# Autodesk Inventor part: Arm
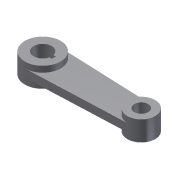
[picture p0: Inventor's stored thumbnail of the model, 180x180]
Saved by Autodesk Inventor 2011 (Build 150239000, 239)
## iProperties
Created: 2009-04
Part Number: Arm
Material: Default
Document SubType Name: Modeling
Designer: Sham
Density: 1 g/cm^3
Sheet Metal Width: 0.000 mm
Sheet Metal Length: 0.000 mm
Sheet Metal Area: 0.000 mm^2
Author: Sham
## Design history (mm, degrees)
sketch "Sketch1"
  geometry: L1 (27.436, 6.3)-(35.136, 6.3); L2 (35.136, 6.3)-(35.136, -6.3); L3 (35.136, -6.3)-(27.436, -6.3); C1 r 56.25 at (0, 0); C2 r 43.75 at (309, 0); C3 r 21.9 at (309, 0); A1 r 28.15 centre (0, 0) between (27.436, 6.3) and (27.436, -6.3); 1 further point
  constraints: 6 end point, 4 centre point, 3 coincident, 2 point on circle, 1 horizontal, 1 parallel, 1 perpendicular, 1 other
  dimensions: "d0" = 112.5 diameter of C1; "d2" = 87.5 diameter of C2; "d3" = 56.3 diameter of A1; "d4" = 43.8 diameter of C3; "d7" = 12.6 distance of L1.end L2.end; "d8" = 7.7 distance of L1.start L1.end; "d9" = 7.7 distance of L2.end L3.end
extrude "Extrusion1" join sketch "Sketch1" stored distance "d5" = 62.5; taper "d6" = 0 deg
sketch "Sketch2"
  geometry: L1 (2.275, 56.204)-(310.77, 43.714); L2 (2.275, -56.204)-(310.77, -43.714); A1 r 56.25 centre (0, 0) between (2.275, 56.204) and (2.275, -56.204) reference; A2 r 43.75 centre (309, 0) between (310.77, 43.714) and (310.77, -43.714) reference
  constraints: 4 end point, 4 point on circle, 4 tangent
extrude "Extrusion2" join sketch "Sketch2" stored distance "d10" = 25; taper "d11" = 0 deg
body "Solid1"
other parameters: "Thickness" = 0.5, "BendRadius" = 0.5 (= Thickness), "BendReliefWidth" = 0.5 (= Thickness), "BendReliefDepth" = 0.25 (= 0.5 x Thickness), "CornerReliefSize" = 2 (= 4 x Thickness), "SeamGap" = 0.01, "MinimumRemnant" = 1 (= 2 x Thickness), "TransitionRadius" = 0.5 (= BendRadius), "JacobiRadiusSize" = 0.5 (= BendRadius), "GapSize" = 0.5 (= Thickness)
